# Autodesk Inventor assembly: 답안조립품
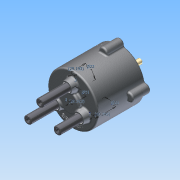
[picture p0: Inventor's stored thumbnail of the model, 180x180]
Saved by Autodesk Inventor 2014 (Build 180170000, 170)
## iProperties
Created: 2015-09
Part Number: 답안조립품
Document SubType Name: Assembly
Designer: study
Mass: 2160.25 g
Surface Area: 1801.17 cm^2
Volume: 438.522 cm^3
Density: 4.9262 g/cm^3
Author: study
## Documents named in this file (14)
- C:\Users\study\Desktop\350916V1024\답안조립품.iam
- C:\Users\study\Desktop\350916V1024\몸체.ipt
- C:\Users\study\Desktop\350916V1024\M5x0.8x20.ipt
- C:\Users\study\Desktop\350916V1024\오일실.ipt
- C:\Users\study\Desktop\350916V1024\커버.ipt
- C:\Users\study\Desktop\350916V1024\멈춤링 10 x 1.ipt
- C:\Users\study\Desktop\350916V1024\멈춤링 22 x 1.2.ipt
- C:\Users\study\Desktop\350916V1024\메인 축.ipt
- C:\Users\study\Desktop\350916V1024\베어링 NA 4900.ipt
- C:\Users\study\Desktop\350916V1024\판캠.ipt
- C:\Users\study\Desktop\350916V1024\가변스프링 - 01.ipt
- C:\Users\study\Desktop\350916V1024\가변스프링 - 02.ipt
- C:\Users\study\Desktop\350916V1024\가변스프링 - 03.ipt
- C:\Users\study\Desktop\350916V1024\슬라이드 축.ipt
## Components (7 placed, 4 different names)
1. 가변스프링 - 01:1
2. 가변스프링 - 02:1
3. 가변스프링 - 03:1
4. M5x0.8x20:1
5. M5x0.8x20:2
6. M5x0.8x20:3
7. M5x0.8x20:4
